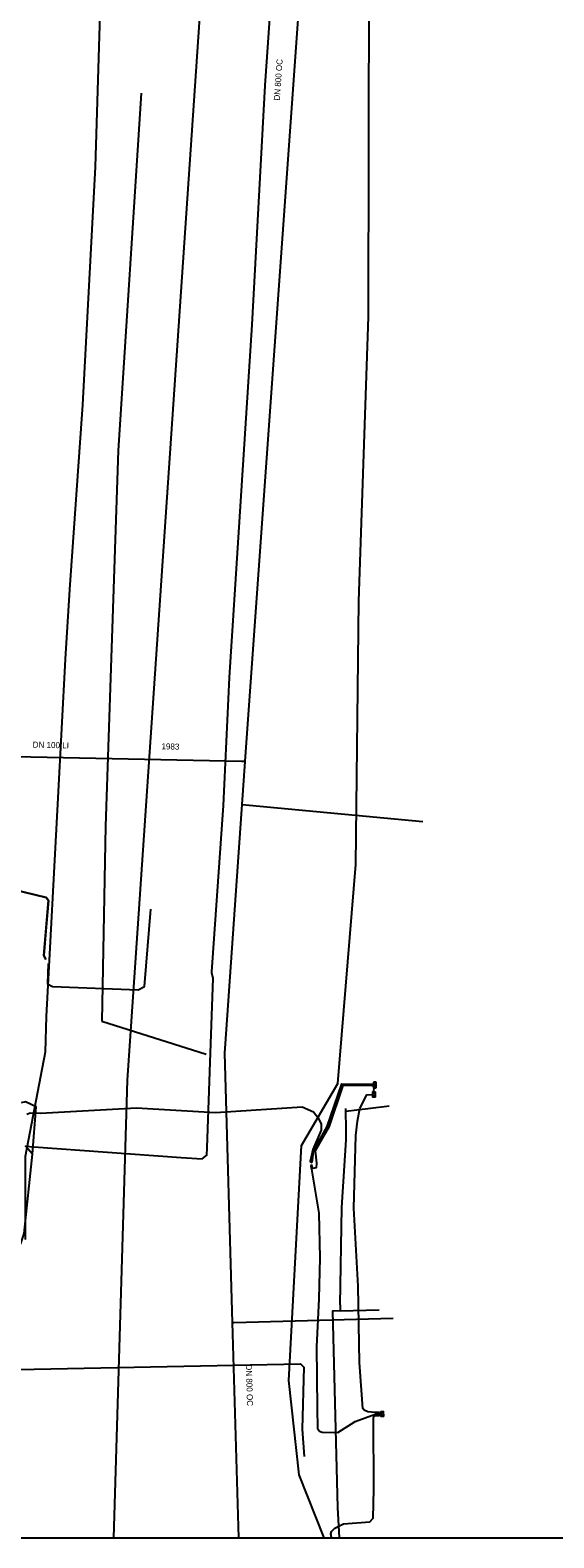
# Model space of a CAD drawing. Extents: x -599951 to -598963, y -1164095 to -1162939.
# Drawn here: x -599201.1 to -599131.5, y -1164094.7 to -1163894.1 of the extents above; entities that cross this region are included whole.
import ezdxf

# ---------------------------------------------------------------- set-up
doc = ezdxf.new("R2010")
doc.units = 0
for name, color, linetype in [('28', 7, 'Continuous'), ('31', 7, 'Continuous'), ('Level 1', 7, 'Continuous'), ('Vrstva 1', 7, 'Continuous'), ('Vrstva 12', 7, 'Continuous'), ('Vrstva 13', 7, 'Continuous'), ('Vrstva 15', 7, 'Continuous'), ('Vrstva 16', 7, 'Continuous'), ('Vrstva 42', 7, 'Continuous'), ('Vrstva 43', 7, 'Continuous'), ('Vrstva 53', 7, 'Continuous'), ('Vrstva 55', 7, 'Continuous')]:
    doc.layers.add(name, color=color, linetype=linetype)

# ---------------------------------------------------------------- blocks, each defined once
blk = doc.blocks.new('NN630')
at = {"layer": '31'}
for points in [[(-0.003, -0.7), (-0.703, 0)], [(-0.703, -0.7), (-0.703, 0), (0.697, 0), (0.697, -0.7)], [(-0.003, -0.7), (0.697, 0)], [(-0.703, -0.7), (0.697, -0.7)]]:
    blk.add_lwpolyline(points, dxfattribs=at)
blk = doc.blocks.new('NN620')
at = {"layer": '28'}
for points in [[(0.752, 0.004), (-0.748, 0.004)], [(-0.748, 0.004), (-0.748, -0.746)], [(0.752, -0.746), (0.752, 0.004)], [(-0.748, -0.746), (0.752, -0.746)], [(0.368, -0.18), (-0.376, -0.18)], [(-0.376, -0.18), (-0.376, -0.558)], [(-0.376, -0.558), (0.368, -0.558)], [(0.321, -0.227), (-0.329, -0.227)], [(-0.329, -0.227), (-0.329, -0.51)], [(-0.329, -0.51), (0.321, -0.51)], [(0.274, -0.274), (-0.281, -0.274)], [(-0.281, -0.274), (-0.281, -0.463)], [(-0.281, -0.463), (0.274, -0.463)], [(0.227, -0.321), (-0.234, -0.321)], [(-0.234, -0.321), (-0.234, -0.416)], [(-0.234, -0.416), (0.227, -0.416)], [(-0.193, -0.369), (0.185, -0.369)], [(0.227, -0.416), (0.227, -0.321)], [(0.274, -0.463), (0.274, -0.274)], [(0.321, -0.51), (0.321, -0.227)], [(0.368, -0.558), (0.368, -0.18)]]:
    blk.add_lwpolyline(points, dxfattribs=at)

msp = doc.modelspace()

# ---------------------------------------------------------------- linework, layer by layer
at = {"layer": 'Level 1'}
msp.add_lwpolyline([(-599189.994, -1164094.695), (-599188.19, -1164033.79), (-599173.8, -1163822.04)], dxfattribs=at)
at = {"layer": 'Vrstva 1'}
for p, q in [((-599186.353, -1163902.508), (-599189.431, -1163950.068)), ((-599189.431, -1163950.068), (-599191.111, -1164000.005)), ((-599191.111, -1164000.005), (-599191.589, -1164025.965)), ((-599191.589, -1164025.965), (-599177.728, -1164030.339))]:
    msp.add_line(p, q, dxfattribs=at)
at = {"layer": 'Vrstva 12'}
msp.add_lwpolyline([(-599207.3, -1164072.41), (-599165.2, -1164071.53), (-599164.75, -1164072.01), (-599164.95, -1164080.22), (-599164.68, -1164083.87)], dxfattribs=at)
at = {"layer": 'Vrstva 13'}
msp.add_line((-599172.525, -1163991.426), (-599172.99, -1163991.41), dxfattribs=at)
for points in [[(-599172.525, -1163991.426), (-599156.29, -1163763.465), (-599155.884, -1163761.839), (-599155.477, -1163760.823), (-599154.329, -1163760.314), (-599145.678, -1163759.782), (-599145.08, -1163759.83)], [(-599172.99, -1163991.41), (-599205.39, -1163990.76), (-599211.34, -1163953.49), (-599216.096, -1163953.719), (-599217.489, -1163953.817), (-599218.011, -1163953.852), (-599218.464, -1163953.886)], [(-599173.394, -1164094.695), (-599174.217, -1164066.069), (-599175.248, -1164030.205), (-599172.926, -1163997.139), (-599172.525, -1163991.426)], [(-599172.926, -1163997.139), (-599171.99, -1163997.23), (-599148.93, -1163999.42)], [(-599174.217, -1164066.069), (-599174.061, -1164066.065), (-599152.886, -1164065.456)]]:
    msp.add_lwpolyline(points, dxfattribs=at)
at = {"layer": 'Vrstva 16'}
for points in [[(-599157.71, -1164037.75), (-599153.71, -1164037.28)], [(-599153.71, -1164037.28), (-599153.39, -1164037.21)], [(-599159.92, -1164063.68), (-599159.71, -1164050.77), (-599159.12, -1164041.76), (-599159.11, -1164040.26), (-599159.16, -1164037.93), (-599159.15, -1164037.6)], [(-599159.16, -1164037.93), (-599157.71, -1164037.75)], [(-599159.92, -1164064.5), (-599160.94, -1164064.52), (-599160.27, -1164090.68), (-599160.063, -1164094.695)], [(-599159.92, -1164063.68), (-599159.92, -1164063.791), (-599159.92, -1164064.5)], [(-599159.92, -1164064.5), (-599154.74, -1164064.38)]]:
    msp.add_lwpolyline(points, dxfattribs=at)
at = {"layer": 'Vrstva 42'}
for points in [[(-599199.062, -1164017.743), (-599199.3, -1164017.23), (-599198.7, -1164009.93), (-599198.98, -1164009.49), (-599204.84, -1164008.1), (-599210.63, -1164005.89), (-599214.09, -1164004.8), (-599215.74, -1164004.56), (-599217.44, -1164014.15), (-599220.88, -1164025.69), (-599232.33, -1164050.83), (-599237.35, -1164060.6), (-599242.04, -1164070.91), (-599244.97, -1164079.21), (-599245.95, -1164082.25), (-599248.54, -1164093.25), (-599248.448, -1164094.695)], [(-599215.74, -1164004.56), (-599214.09, -1164004.8), (-599210.63, -1164005.89), (-599204.84, -1164008.1), (-599198.98, -1164009.49), (-599198.7, -1164009.93), (-599198.99, -1164013.4), (-599199.3, -1164017.23), (-599199.062, -1164017.743)], [(-599199.062, -1164017.743), (-599199.3, -1164017.23), (-599198.7, -1164009.93), (-599198.98, -1164009.49), (-599204.84, -1164008.1)], [(-599198.75, -1164018.3), (-599198.84, -1164021.01), (-599198.16, -1164021.35), (-599186.78, -1164021.79), (-599185.92, -1164021.34), (-599185.095, -1164011.059)], [(-599198.75, -1164018.3), (-599198.84, -1164021.01), (-599198.16, -1164021.35), (-599186.78, -1164021.79), (-599185.92, -1164021.34), (-599185.095, -1164011.059)], [(-599198.75, -1164018.3), (-599198.84, -1164021.01), (-599198.16, -1164021.35), (-599186.78, -1164021.79), (-599185.92, -1164021.34), (-599185.095, -1164011.059)], [(-599155.496, -1164034.551), (-599155.681, -1164034.549), (-599159.558, -1164034.521), (-599161.438, -1164040.071), (-599162.113, -1164041.26), (-599163.254, -1164043.201), (-599163.04, -1164044.87), (-599163.11, -1164045.47), (-599163.56, -1164045.54), (-599163.72, -1164045.04)], [(-599163.65, -1164044.76), (-599163.426, -1164043.099), (-599162.287, -1164041.16), (-599161.622, -1164039.989), (-599159.702, -1164034.319), (-599155.653, -1164034.349), (-599155.49, -1164034.347)], [(-599155.499, -1164034.845), (-599155.43, -1164034.93), (-599155.558, -1164035.7)], [(-599201.59, -1164038.32), (-599201.12, -1164038.16), (-599199.76, -1164038.19), (-599186.98, -1164037.5), (-599185.51, -1164037.56), (-599176.48, -1164038.11), (-599164.98, -1164037.36), (-599163.47, -1164038.02), (-599162.85, -1164038.82), (-599162.46, -1164039.66), (-599162.44, -1164040.45), (-599163.54, -1164043.039), (-599163.887, -1164044.63), (-599163.65, -1164044.76)], [(-599154.468, -1164078.222), (-599154.577, -1164078.119), (-599154.79, -1164078.021), (-599155.276, -1164078.02), (-599156.25, -1164077.92), (-599156.73, -1164077.71), (-599156.91, -1164077.51), (-599157.36, -1164071.36), (-599157.53, -1164061.2), (-599158.09, -1164050.86), (-599157.84, -1164041.19), (-599157.62, -1164039.28), (-599157.3, -1164037.59), (-599156.38, -1164035.78), (-599155.558, -1164035.7)], [(-599163.72, -1164045.04), (-599163.805, -1164045.232), (-599163.724, -1164045.65), (-599162.74, -1164051.49), (-599162.6, -1164057.45), (-599162.75, -1164062.91), (-599163.07, -1164069.27), (-599162.96, -1164077.39), (-599162.91, -1164080.14), (-599162.68, -1164080.5), (-599162.32, -1164080.63), (-599160.2, -1164080.7), (-599157.93, -1164079.22), (-599155.24, -1164078.22), (-599154.468, -1164078.222)], [(-599161.049, -1164094.695), (-599161.07, -1164094.67), (-599161.14, -1164094.18), (-599161.05, -1164093.86), (-599160.6, -1164093.42), (-599159.45, -1164092.85), (-599155.97, -1164092.57), (-599155.52, -1164092.08), (-599155.45, -1164088.24), (-599155.48, -1164078.8), (-599155.423, -1164078.501), (-599155.204, -1164078.42), (-599154.787, -1164078.421), (-599154.571, -1164078.331), (-599154.468, -1164078.222)]]:
    msp.add_lwpolyline(points, dxfattribs=at)
at = {"layer": 'Vrstva 53'}
msp.add_lwpolyline([(-599951.125, -1164094.695), (-598963.215, -1164094.695), (-598963.215, -1162939.4), (-599951.125, -1162939.4)], close=True, dxfattribs=at)
at = {"layer": 'Vrstva 55'}
for points in [[(-599162.057, -1164094.695), (-599165.35, -1164086.32), (-599166.73, -1164073.75), (-599165.047, -1164042.51), (-599160.24, -1164034.269), (-599157.836, -1164005.125), (-599157.45, -1163970.102), (-599156.162, -1163932.245), (-599156.04, -1163887.22), (-599152.39, -1163841.5), (-599149.466, -1163804.768), (-599147.296, -1163778.87), (-599143.812, -1163767.118), (-599138.093, -1163729.181), (-599134.088, -1163691.818), (-599133.543, -1163671.755), (-599132.377, -1163651.32), (-599127.82, -1163630.46), (-599126.99, -1163630.61)], [(-599176.967, -1164019.522), (-599176.964, -1164019.42), (-599175.409, -1163997.267), (-599174.614, -1163980.264), (-599171.61, -1163933.32), (-599169.898, -1163901.497), (-599167.091, -1163861.357), (-599162.51, -1163804.89), (-599158.142, -1163745.809), (-599157.22, -1163741.2), (-599156.59, -1163732.53), (-599156.662, -1163727.765), (-599157.054, -1163727.764)], [(-599201.77, -1164055.01), (-599201.73, -1164043.92), (-599199.084, -1164030.063), (-599198.94, -1164025.337), (-599197.401, -1163996.256), (-599196.422, -1163977.827), (-599195.864, -1163968.523), (-599194.12, -1163943.99), (-599192.431, -1163912.296), (-599191.573, -1163883.274), (-599189.739, -1163853.571), (-599187.709, -1163825.843), (-599187.581, -1163824.169)], [(-599201.91, -1164054.19), (-599200.8, -1164043.64), (-599201.75, -1164042.57), (-599200.62, -1164042.69), (-599181.06, -1164044.091), (-599178.28, -1164044.29), (-599177.64, -1164043.79), (-599177.59, -1164042.83), (-599177.23, -1164032.683), (-599176.877, -1164022.742), (-599176.79, -1164020.29), (-599176.98, -1164019.53)], [(-599223.255, -1164081.169), (-599222.89, -1164081.03), (-599221.55, -1164081.19), (-599219.04, -1164080.11), (-599217.54, -1164079), (-599214.35, -1164075.25), (-599211.56, -1164070.97), (-599209.83, -1164067.15), (-599208.27, -1164061.95), (-599208.02, -1164058.99), (-599207.89, -1164058.32), (-599207.11, -1164057.71), (-599205.57, -1164057.27), (-599202.37, -1164055.53), (-599201.91, -1164054.19), (-599200.8, -1164043.64), (-599200.35, -1164037.34), (-599201.76, -1164036.7), (-599202.328, -1164036.827)]]:
    msp.add_lwpolyline(points, dxfattribs=at)

# ---------------------------------------------------------------- block references
at = {"layer": 'Vrstva 43'}
for name, p, xscale, yscale, rotation in [('NN630', (-599155.559, -1164035.7), 0.5, 0.5, 90), ('NN620', (-599155.49, -1164034.45), 0.5, 0.5, 89), ('NN630', (-599154.468, -1164078.222), 0.5000000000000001, 0.4999999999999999, 92)]:
    msp.add_blockref(name, p, dxfattribs=dict(at, xscale=xscale, yscale=yscale, rotation=rotation))

# ---------------------------------------------------------------- texts
at = {"layer": 'Vrstva 15'}
for s, rotation, p in [('DN 800 OC', 85.94367, (-599167.944, -1163903.512)), ('DN 100 LI', 358.84347, (-599200.796, -1163989.573)), ('1983', 358.84347, (-599183.678, -1163989.797)), ('DN 800 OC', 271.63929, (-599172.452, -1164071.649))]:
    msp.add_text(s, height=0.8, rotation=rotation, dxfattribs=at).set_placement(p)

doc.saveas('drawing.dxf')
